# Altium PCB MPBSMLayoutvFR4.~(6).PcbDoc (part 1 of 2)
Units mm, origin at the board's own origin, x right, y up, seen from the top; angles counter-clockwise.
Board outline 131.7 x 110.39 mm, 4 copper layers (Top Layer, Power, GroundPlane, Bottom Layer), stack 2.286 mm thick; 158 components, 77 nets, 433 pads, 117 vias.
Unrouted connection lines stored in the file: 49.
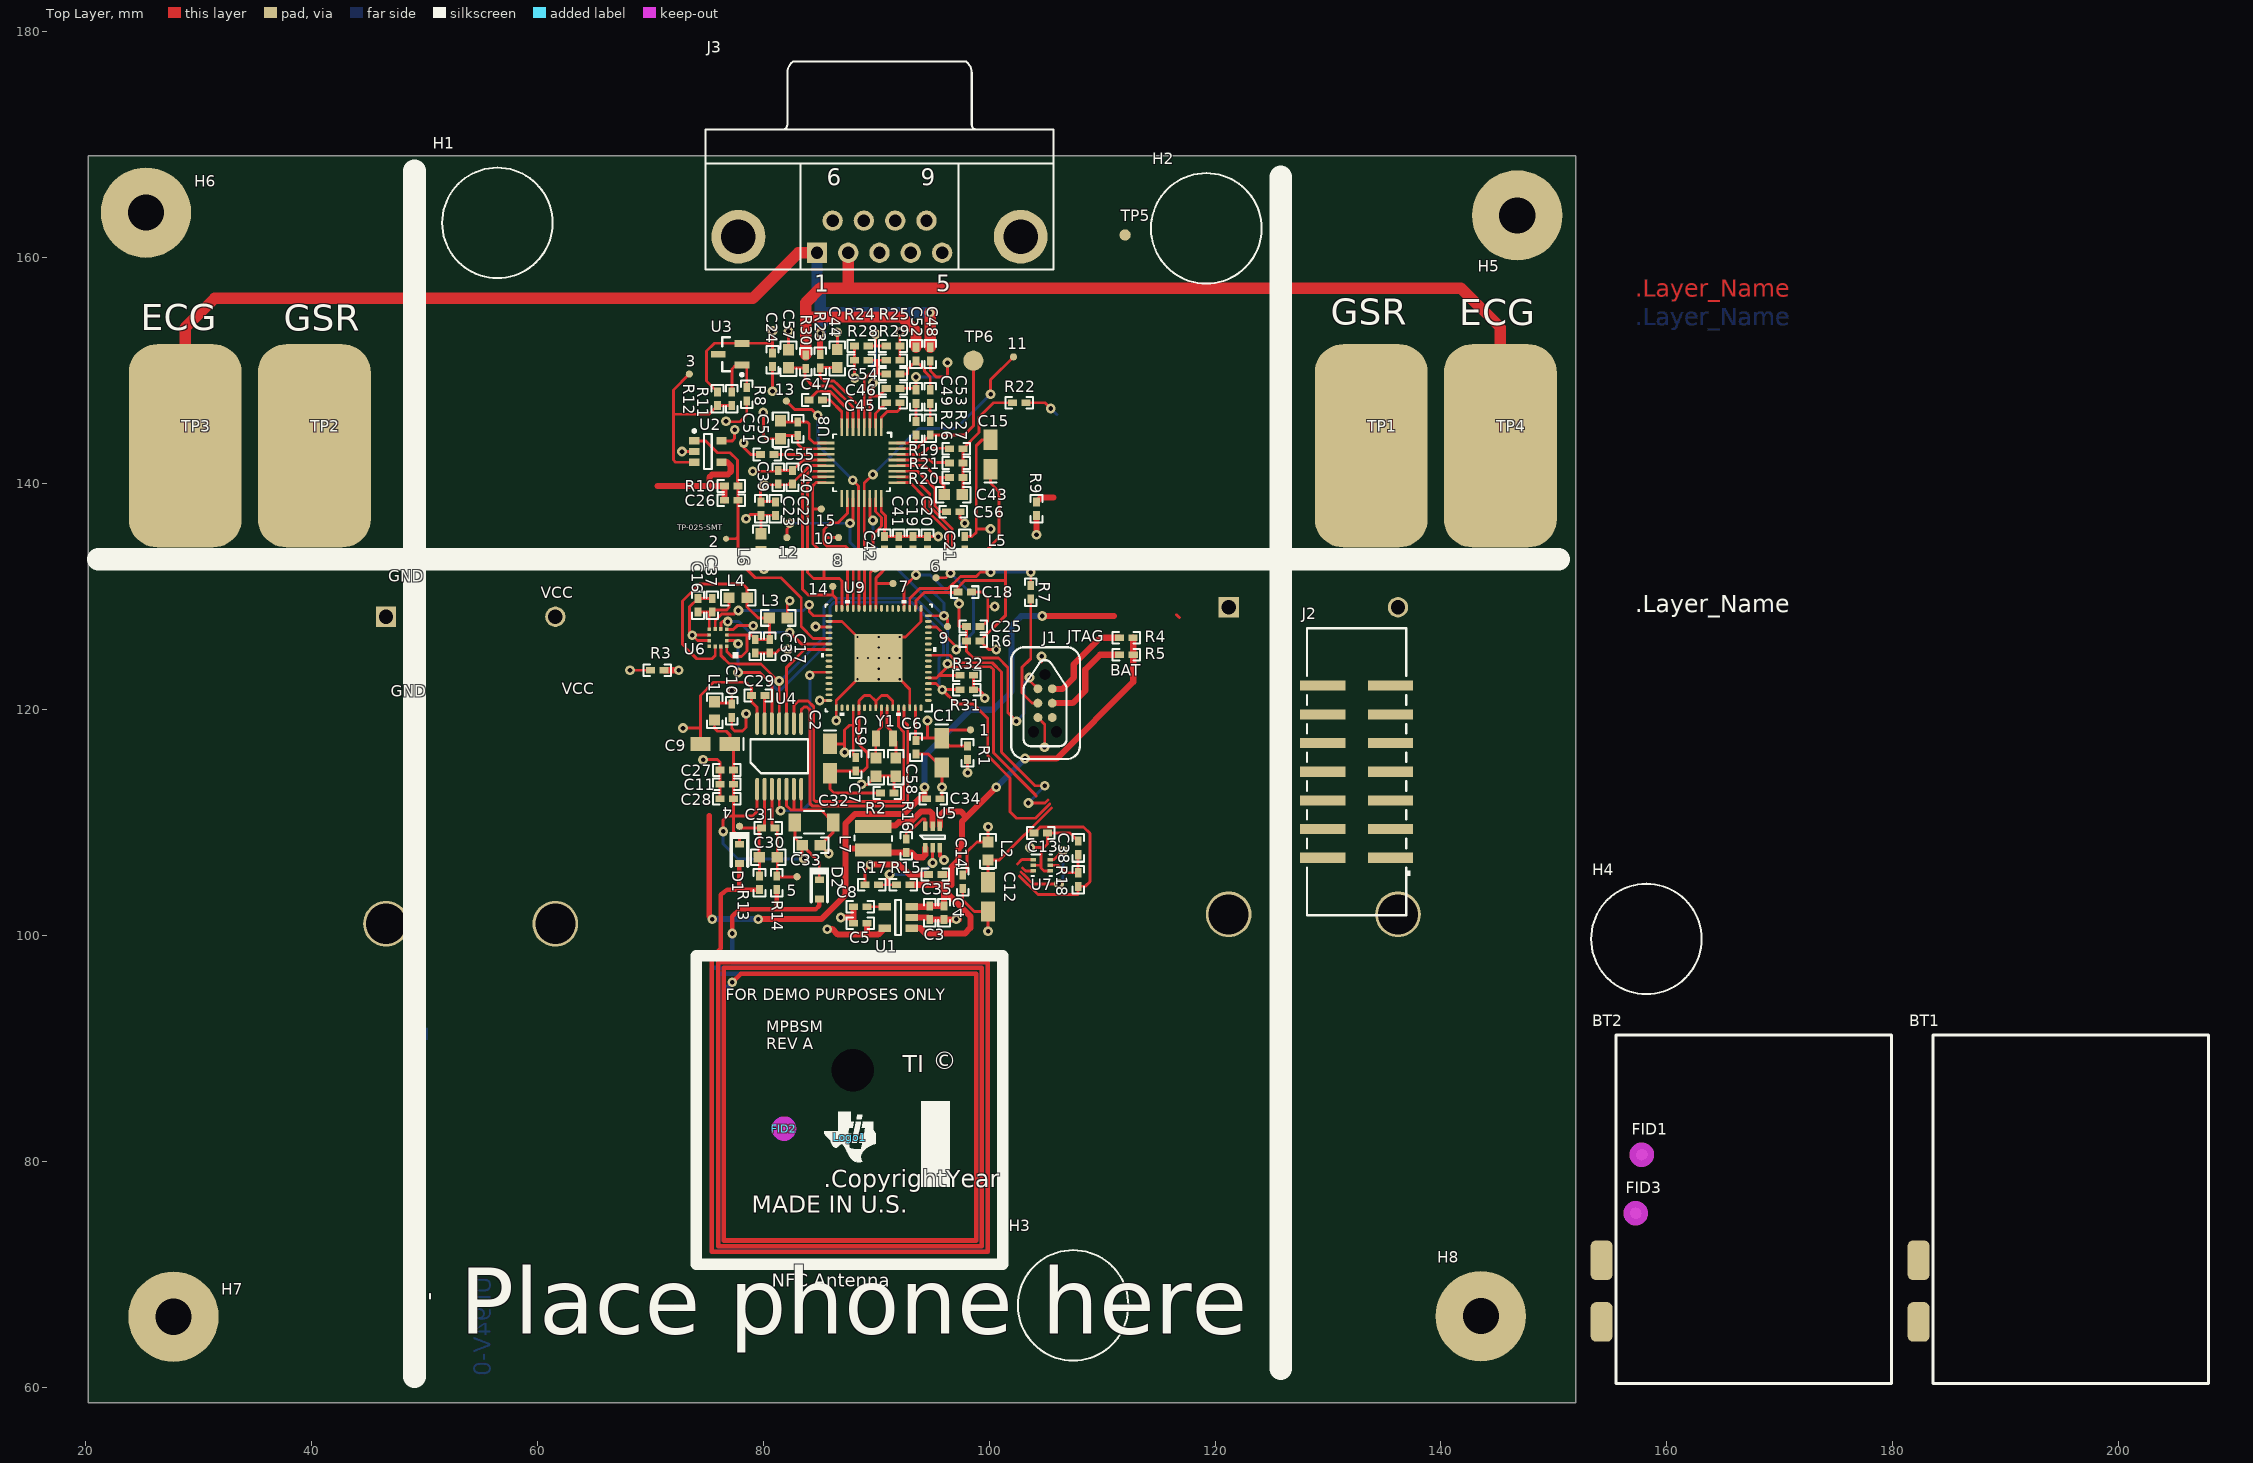
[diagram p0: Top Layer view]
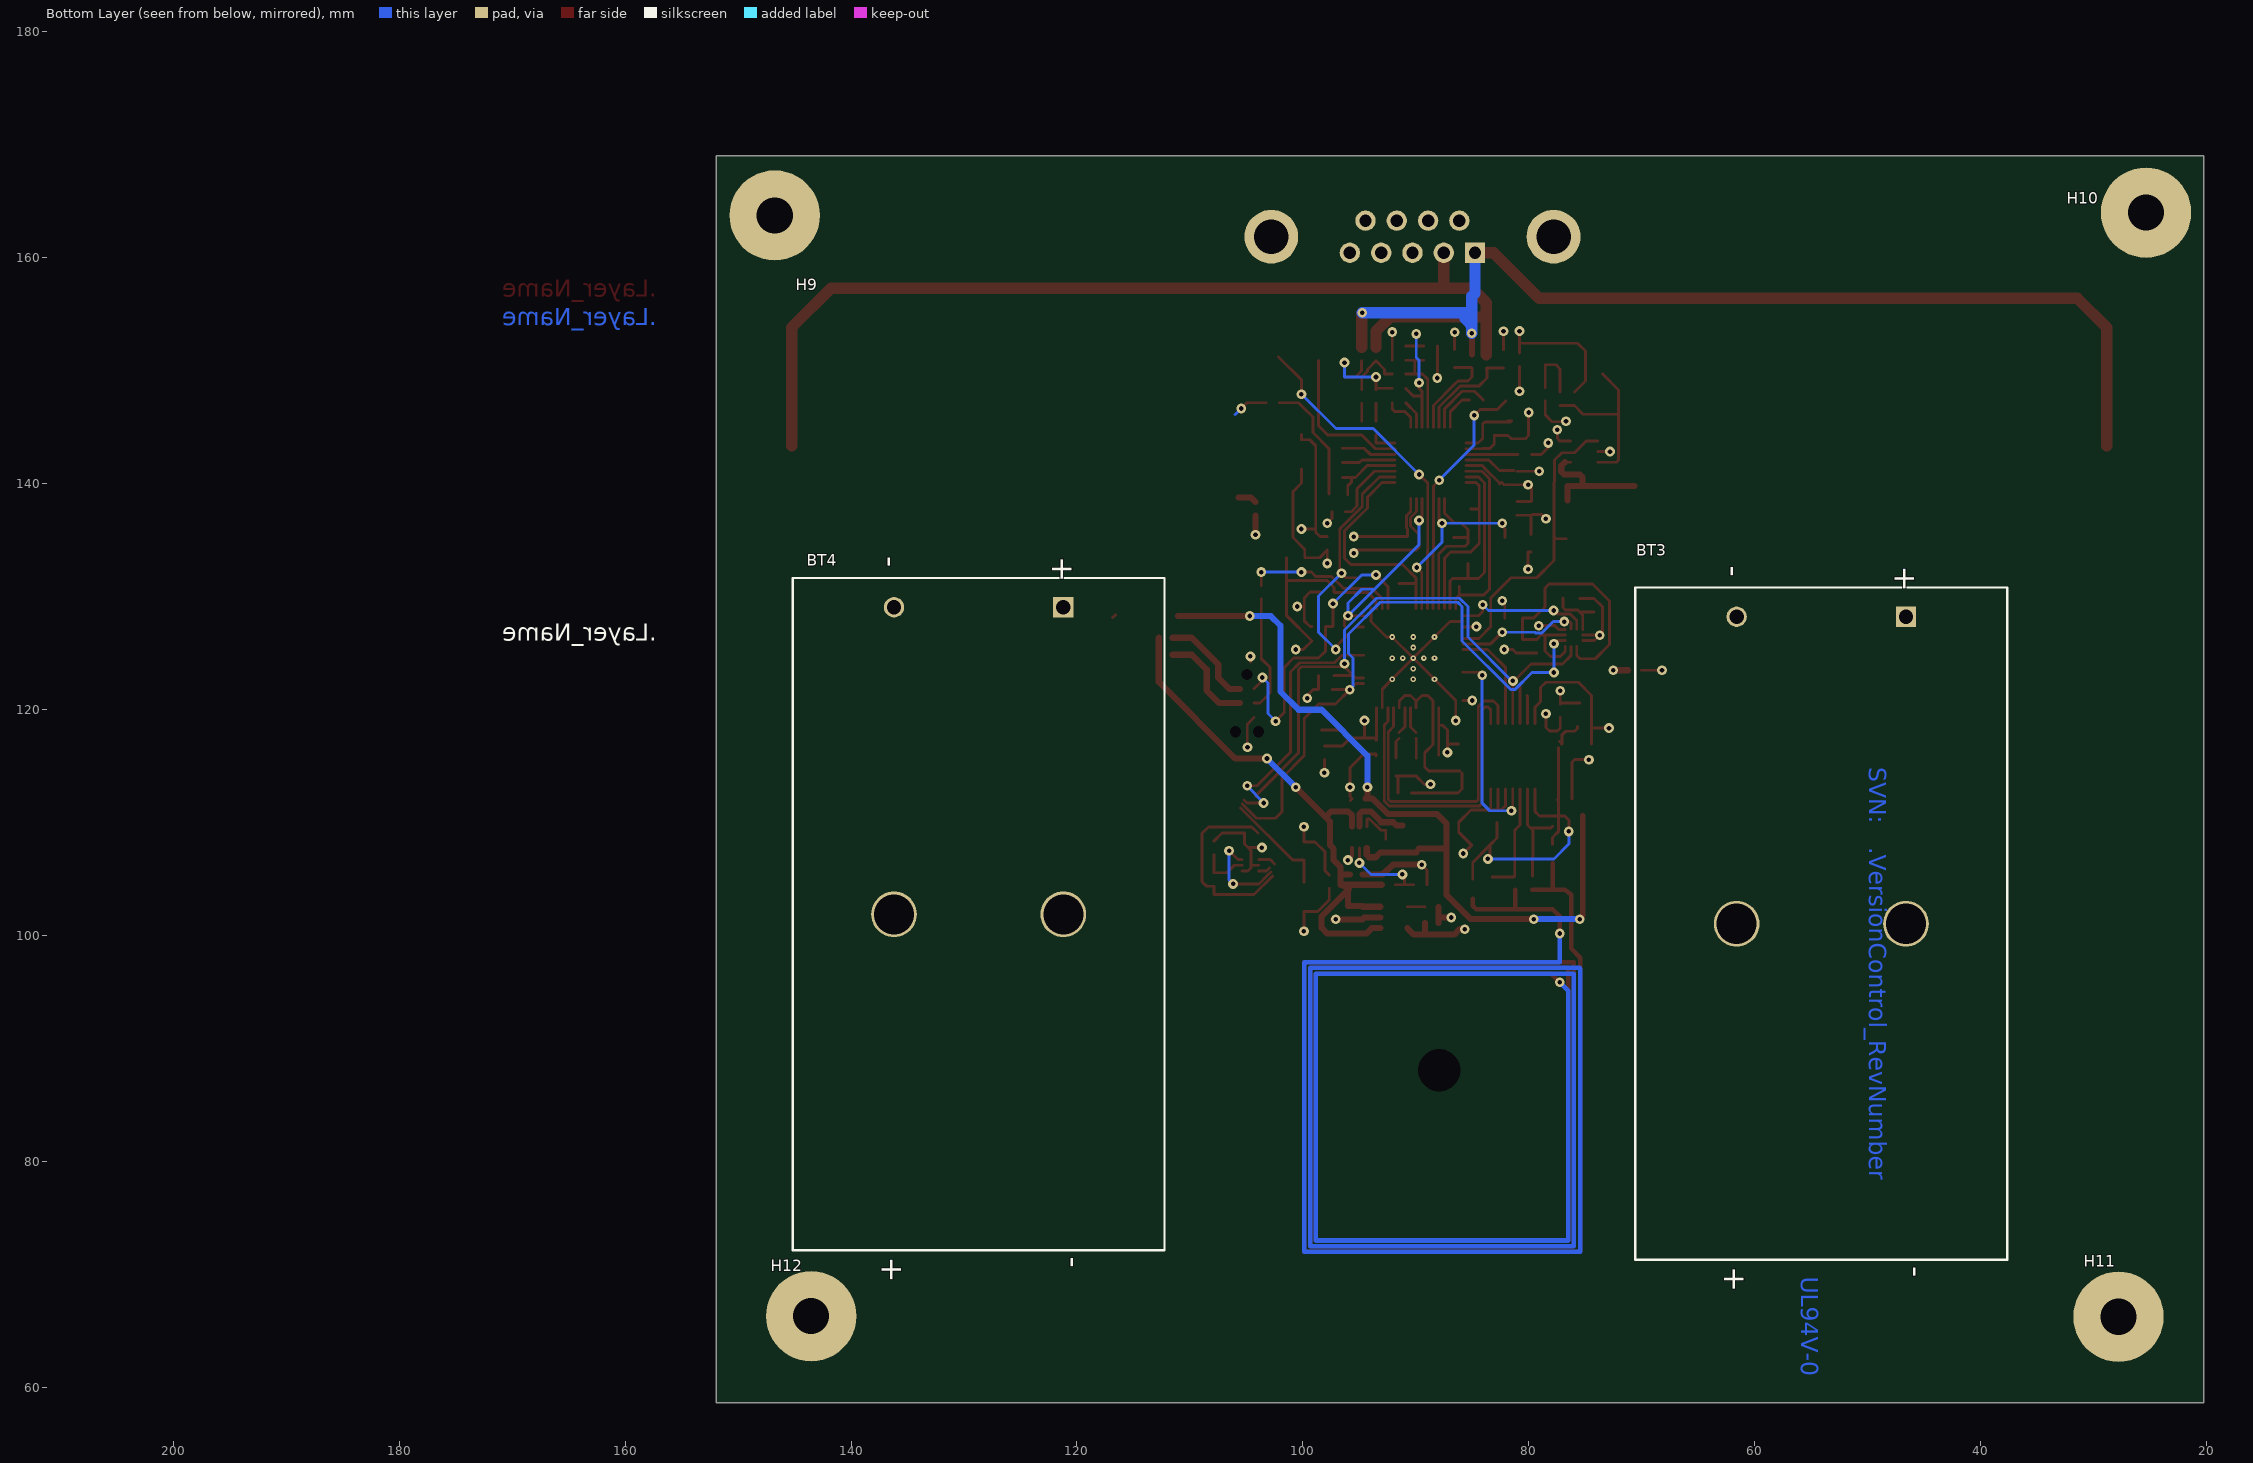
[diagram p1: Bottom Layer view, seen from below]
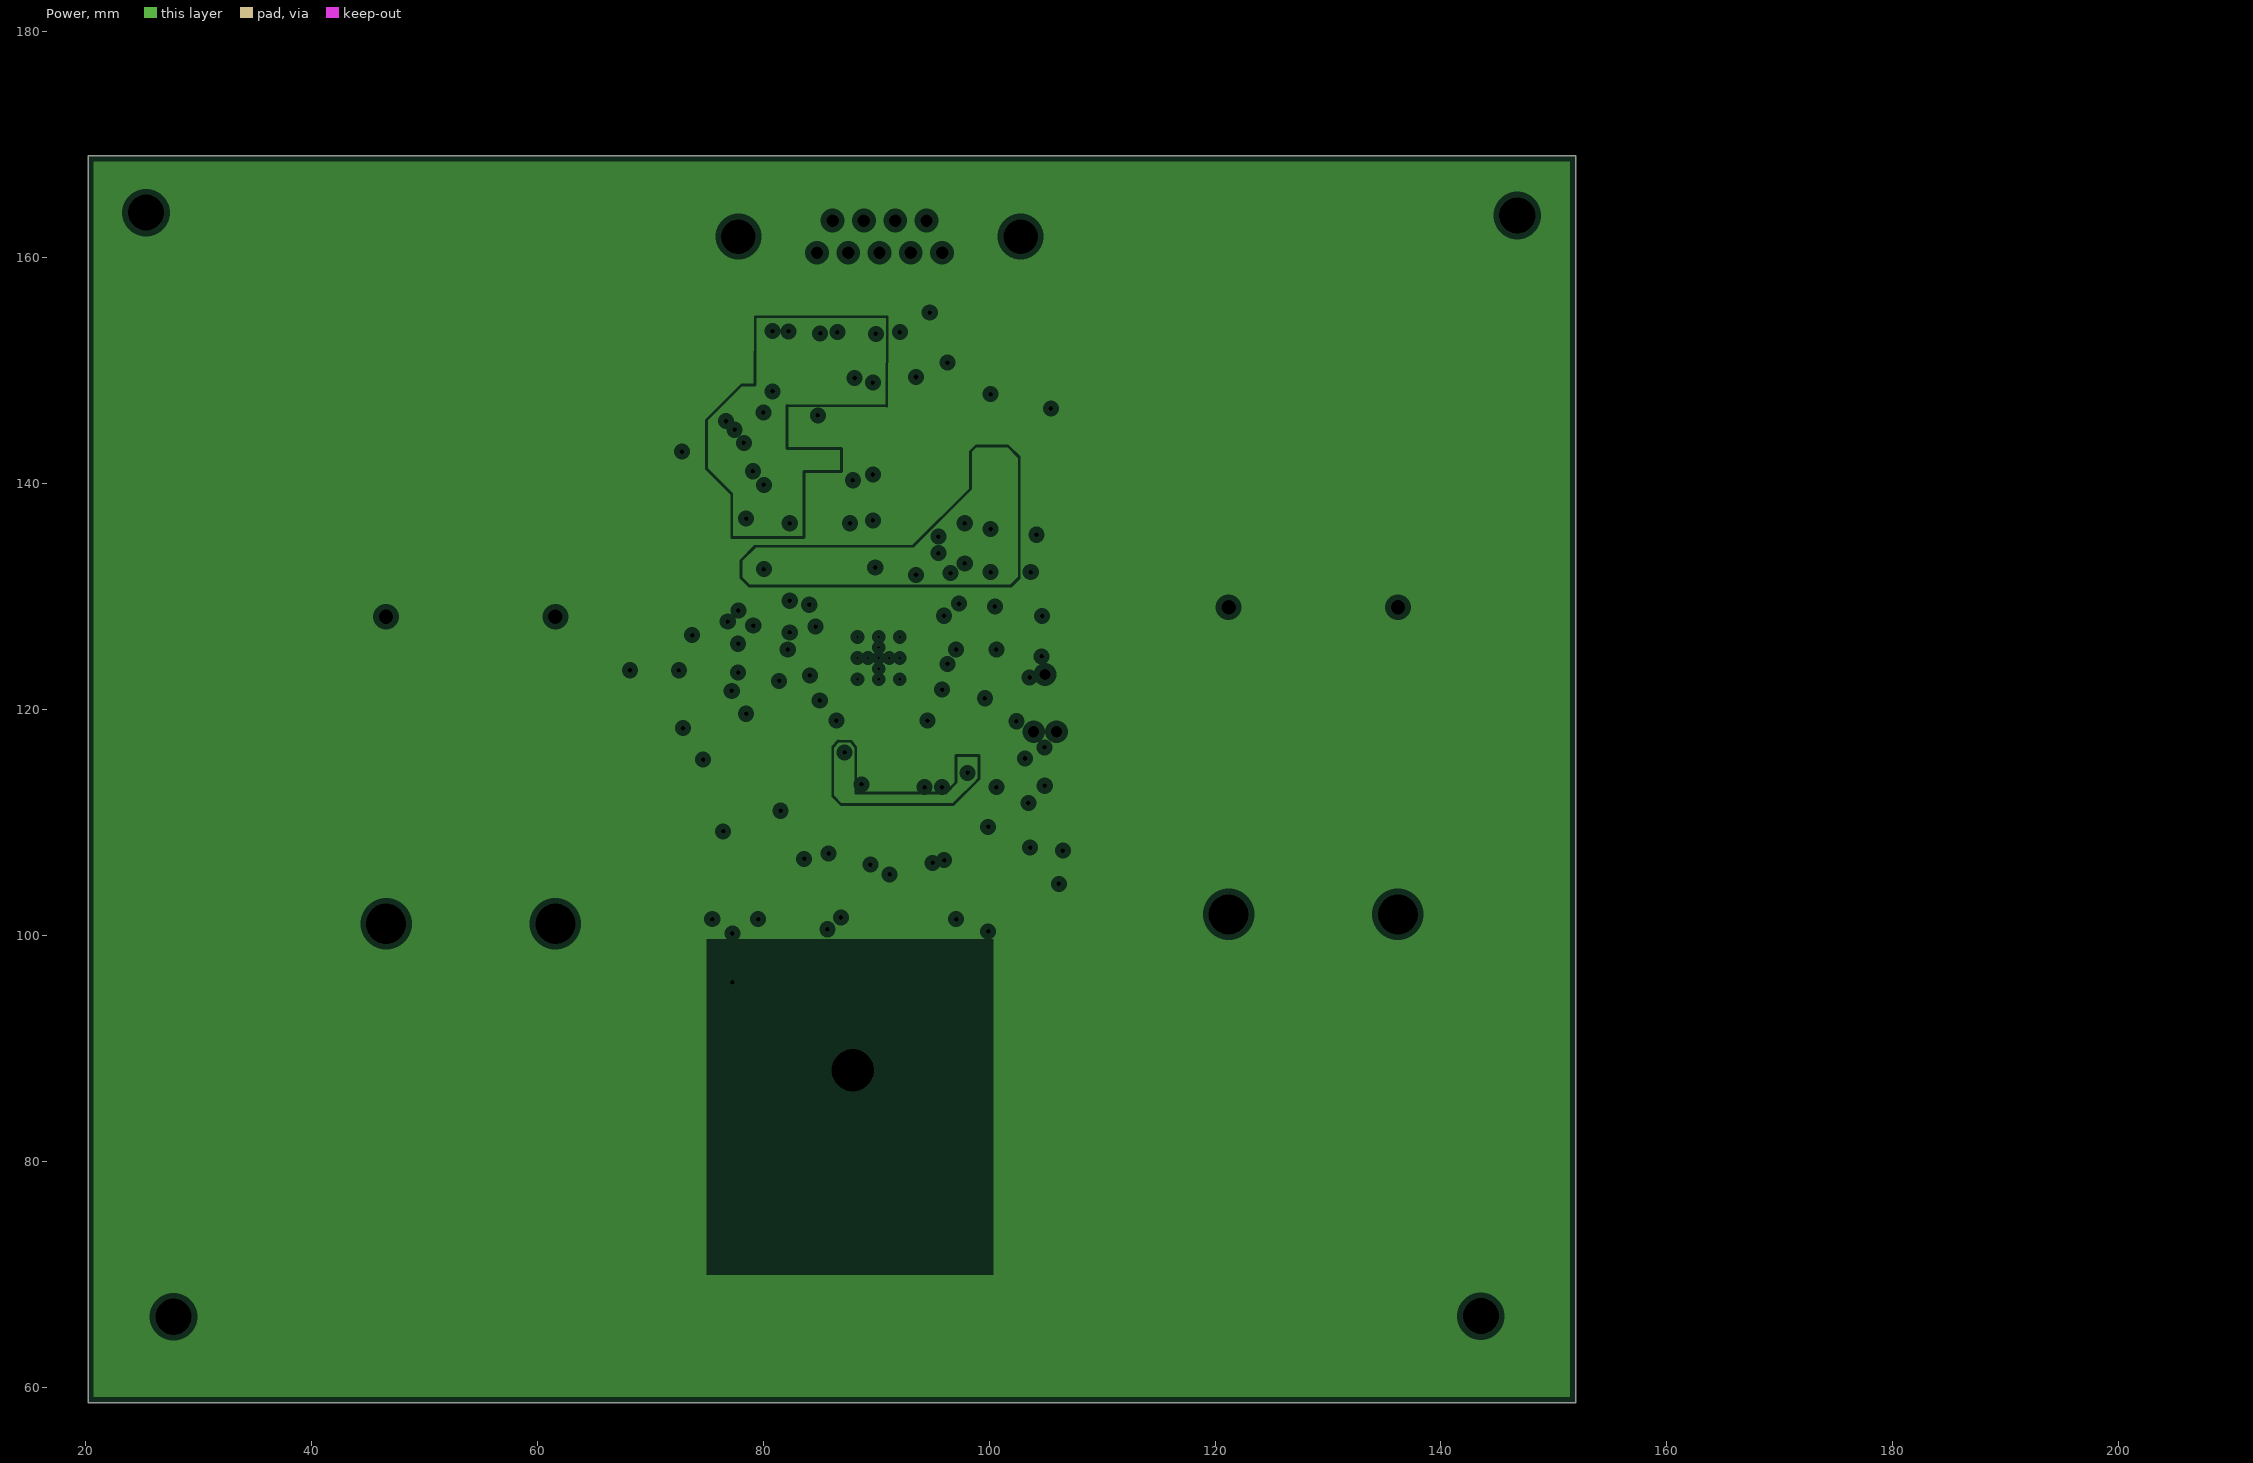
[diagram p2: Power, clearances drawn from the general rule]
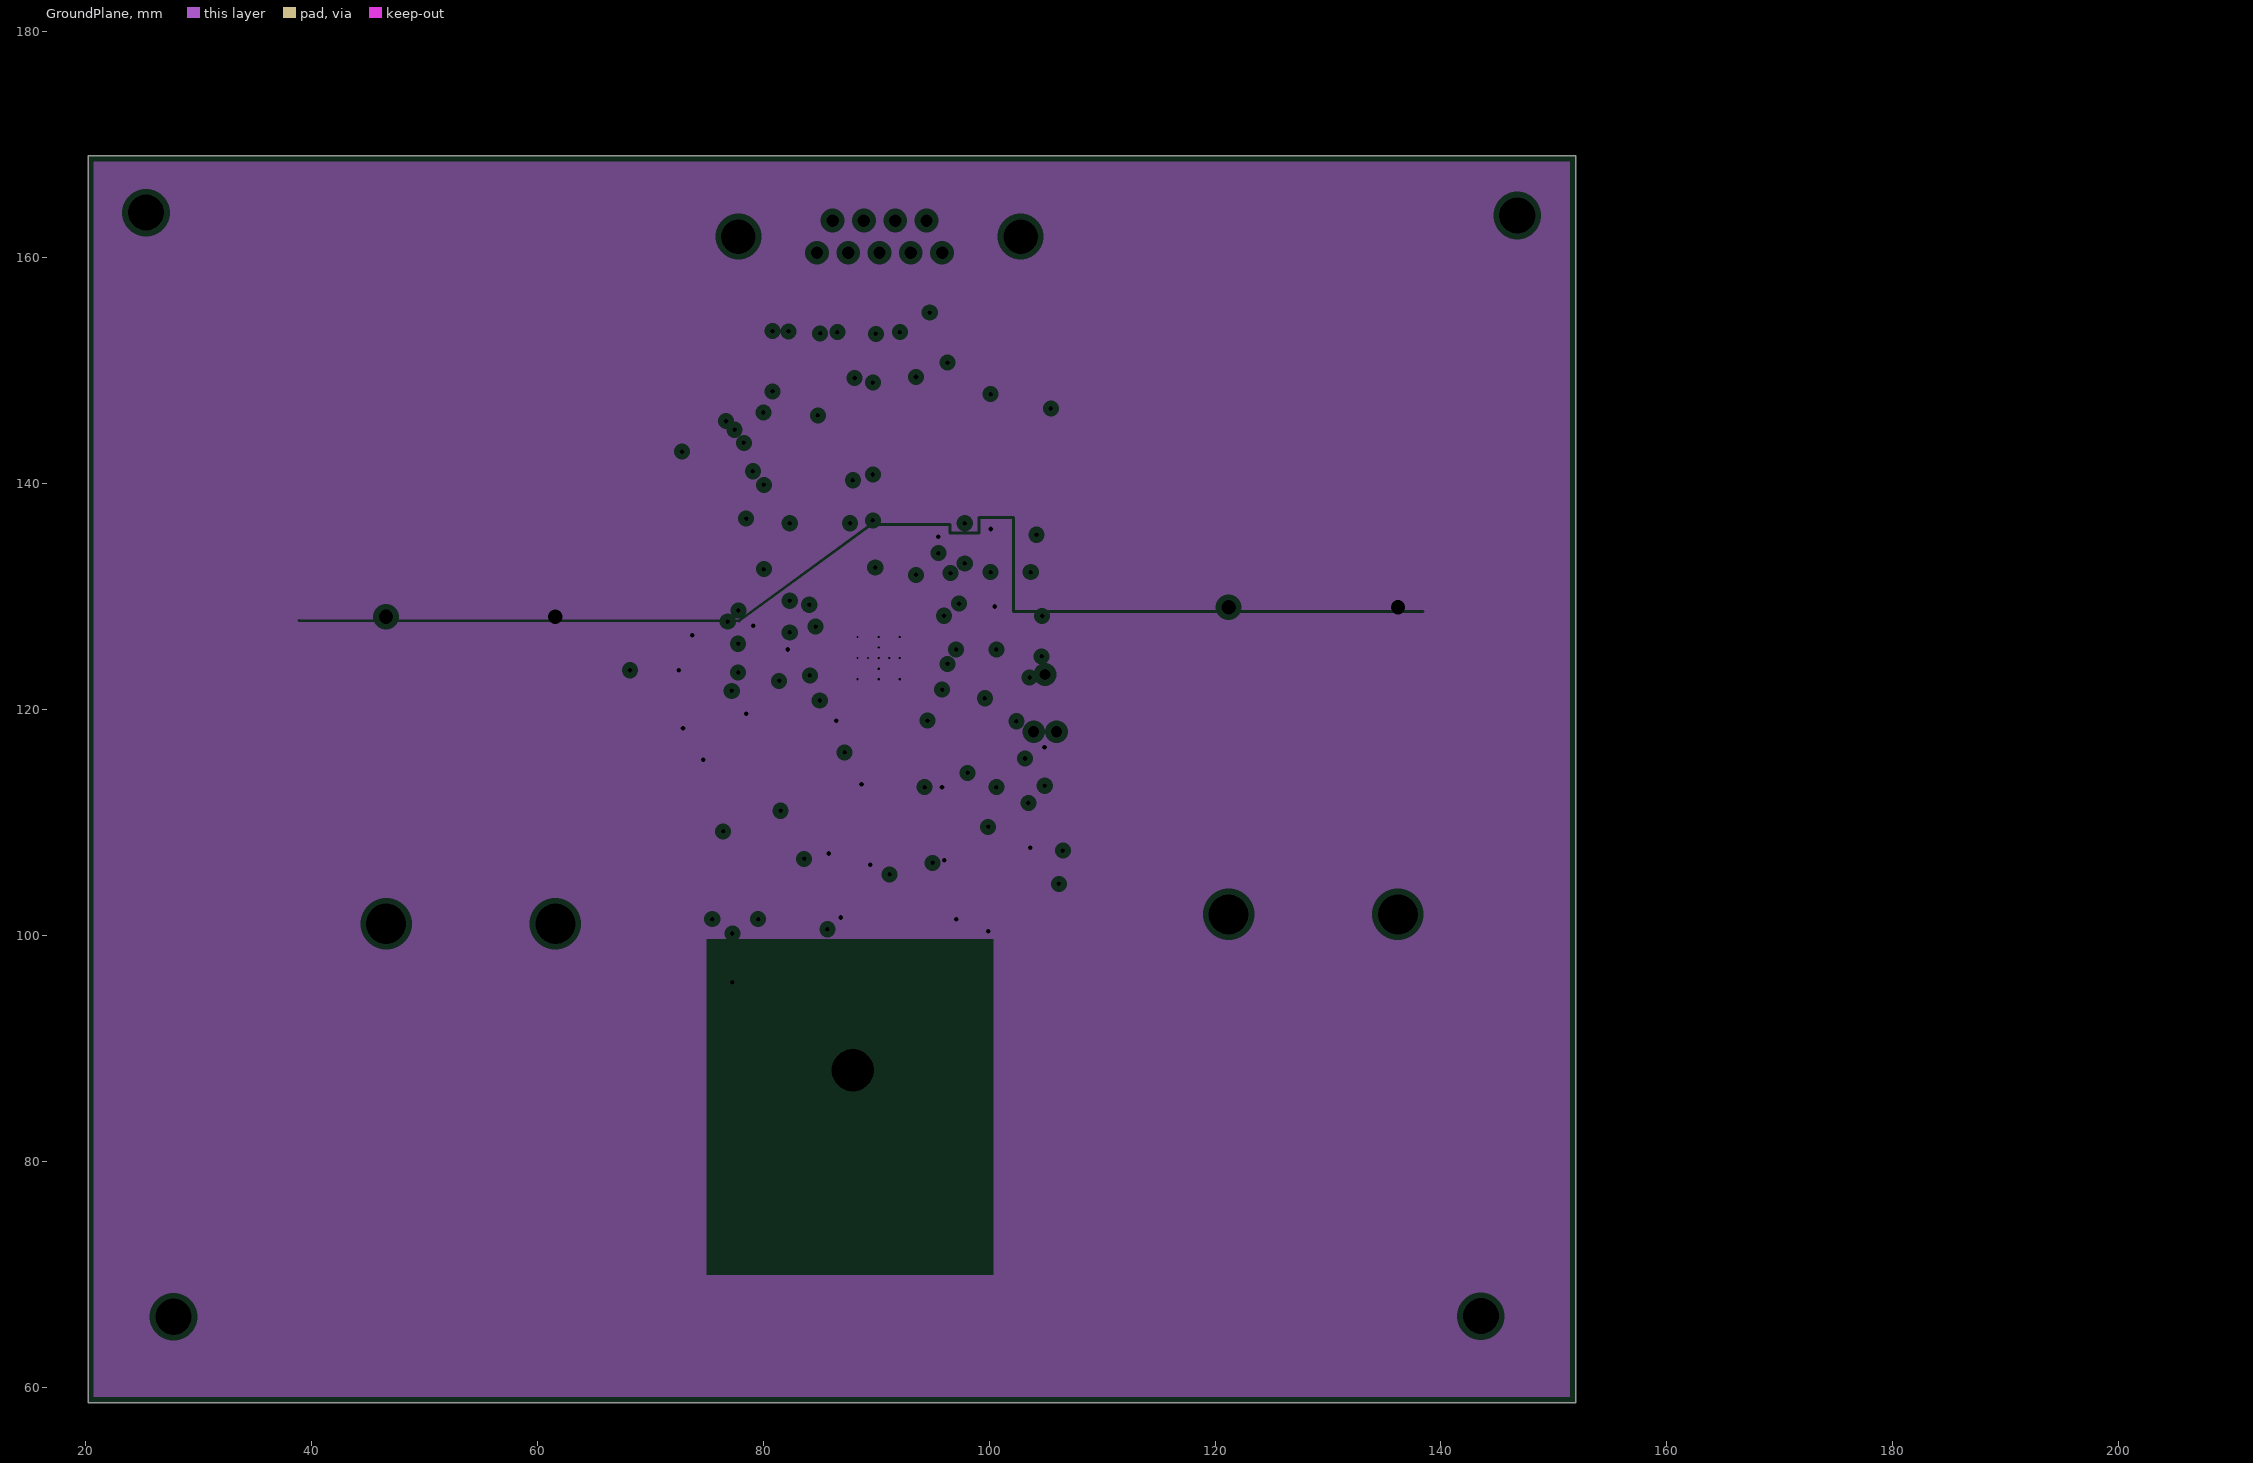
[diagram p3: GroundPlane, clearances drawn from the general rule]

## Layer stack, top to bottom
Top Solder: solder mask 0.0102, Solder Resist, Dk 3.5
Top Layer: signal copper 0.0356
Dielectric1: core 1.5037, FR-4, Dk 4.8
Power: plane copper 0.0356
Dielectric2: prepreg 0.32, FR-4, Dk 4.8
GroundPlane: plane copper 0.0356, net GND
Dielectric3: core 0.32, FR-4, Dk 4.8
Bottom Layer: signal copper 0.0356
Bottom Solder: solder mask 0.0102, Solder Resist, Dk 3.5

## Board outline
20.218,169.037 20.218,58.649 150.825,58.649 151.917,58.649 151.917,158.471 151.917,169.037 20.218,169.037

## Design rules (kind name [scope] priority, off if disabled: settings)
AcuteAngle [All] p1: minimum=4.50000000000000E+0001 checktracksonly=FALSE
AssemblyTestPointUsage [All] p1: valid=2
Clearance Clearance_BoardEdge_MountingHoles [OnCopper and InComponentClass('Mounting Holes') vs IsKeepOut] p1: gap=1.016
Clearance Clearance_BoardEdge_Poly [OnCopper and InPoly vs IsKeepOut] p2: gap=0.635
Clearance Clearance_BoardEdge [OnCopper and Not InComponentClass('Logo') and not InComponentClass('FiducialMark') and not InRegion(1000,500,4000,800) and Not IsKeepout vs IsKeepOut] p3: gap=1.905
Clearance Clearance_Poly [InPolygon] p4: gap=0.635
Clearance [All] p5: gap=0.1
ComponentClearance ComponentClearance_Shunt [InComponentClass('Header') vs InComponentClass('Shunt')] p1: gap=0 collisioncheckmode=3 verticalgap=0 showdistances=FALSE
ComponentClearance ComponentClearance_MountingHoles_FiducialMarks [InComponentClass('Mounting Holes') vs InComponentClass('FiducialMark')] p2: gap=1.27 collisioncheckmode=3 verticalgap=0.254 showdistances=FALSE
ComponentClearance ComponentClearance_Logo [InComponentClass('Logo')] p3: gap=1.27 collisioncheckmode=3 verticalgap=0.254 showdistances=FALSE
ComponentClearance ComponentClearance_ScrewToNut [(HasFootprint('NY PMS 440 0025 PH')) vs (HasFootprint('Keystone_1902C'))] p4: gap=0.127 collisioncheckmode=3 verticalgap=0.254 showdistances=FALSE
ComponentClearance ComponentClearance_MountingHoles [InComponentClass('Mounting Holes')] p5: gap=6.35 collisioncheckmode=3 verticalgap=2540 showdistances=FALSE
ComponentClearance ComponentClearance_SmallPassives [HasFootprint('0201*') or HasFootprint('0402*') or HasFootprint('0508') or HasFootprint('0603*') or HasFootprint('0612') or HasFootprint('0805*') or HasFootprint('0815*') or HasFootprint('0830*') or HasFootprint('1206*') or HasFootprint('1210*') or HasFootprint('1808*') or HasFootprint('1812*') or HasFootprint('1825*') or HasFootprint('2010*') or HasFootprint('2220*') or HasFootprint('2225*') or HasFootprint('2512*') or HasFootprint('2728*') or HasFootprint('3518*') vs HasFootprint('0201*') or HasFootprint('0402*') or HasFootprint('0508') or HasFootprint('0603*') or HasFootprint('0612') or HasFootprint('0805*') or HasFootprint('0815*') or HasFootprint('0830*') or HasFootprint('1206*') or HasFootprint('1210*') or HasFootprint('1808*') or HasFootprint('1812*') or HasFootprint('1825*') or HasFootprint('2010*') or HasFootprint('2220*') or HasFootprint('2225*') or HasFootprint('2512*') or HasFootprint('2728*') or HasFootprint('3518*')] p6: gap=0.508 collisioncheckmode=3 verticalgap=0.254 showdistances=FALSE
ComponentClearance ComponentClearance_THtoSMT [IsThruComponent vs IsSMTComponent] p7: gap=2.54 collisioncheckmode=3 verticalgap=0.762 showdistances=FALSE
ComponentClearance ComponentClearance_THtoTH [IsThruComponent vs IsThruComponent] p8: gap=3 collisioncheckmode=3 verticalgap=0.762 showdistances=FALSE
ComponentClearance [All] p9: gap=1.016 collisioncheckmode=3 verticalgap=0.254 showdistances=FALSE
DiffPairsRouting [All] p1: maxlimit=2.54 minlimit=0.254 mostfreqgap=0.254 toplayer_minwidth=0.381 toplayer_maxwidth=0.381 toplayer_prefwidth=0.381 bottomlayer_minwidth=0.381 bottomlayer_maxwidth=0.381 bottomlayer_prefwidth=0.381 maxuncoupledlength=25.4
FabricationTestPointUsage TestPointUsage [All] p1: valid=2 allowmultiple=FALSE
FabricationTestpoint Testpoint [All] p1: side=3 testpointundercomponent=TRUE minsize=1.016 maxsize=2.54 preferedsize=1.524 minholesize=0 maxholesize=1.016 preferedholesize=0.813 testpointgrid=0.025 allowsidetop=TRUE allowsidebottom=TRUE usegrid=TRUE gridtolerance=0
FanoutControl Fanout_LCC [IsLCC] p1: bgadir=Out bgaviamode=Centered fanoutstyle=Auto fanoutdirection=Alternating viagrid=0.025 // Fanout_LCC (Default Rule)
FanoutControl Fanout_BGA [IsBGA] p2: bgadir=Out bgaviamode=Centered fanoutstyle=Auto fanoutdirection=Alternating viagrid=0.025 // Fanout_BGA (Default Rule)
FanoutControl Fanout_Default [All] p4: bgadir=Out bgaviamode=Centered fanoutstyle=Auto fanoutdirection=Alternating viagrid=0.025 // Fanout_Default (Default Rule)
FanoutControl Fanout_Small [(CompPinCount < 5)] p5: bgadir=Out bgaviamode=Centered fanoutstyle=Auto fanoutdirection=OutThenIn viagrid=0.025 // Fanout_Small (Default Rule)
Height [All] p1: minheight=0 maxheight=55.4 prefheight=12.7
HoleSize [All] p1: absolutevalues=TRUE maxlimit=6.375 minlimit=0.1 maxpercent=80.000 minpercent=20.000
MinimumAnnularRing MinimumAnnularRing_ThermalPadVias [IsVia and InAnyComponent] p1: minimumring=0.15
MinimumAnnularRing [All] p2: minimumring=0.229
MinimumSolderMaskSliver MinimumSolderMaskSliver_Logo [InComponentClass('Logo') vs InComponentClass('Logo')] p1: minsoldermaskwidth=0.018
MinimumSolderMaskSliver [All] p2: minsoldermaskwidth=0.08
PlaneClearance [All] p1: clearance=0.508
PlaneConnect [All] p1: planeconnectstyle=Relief reliefexpansion=0.254 reliefentries=4 reliefconductorwidth=0.254 reliefairgap=0.254
PolygonConnect [All] p1: connectstyle=Relief reliefconductorwidth=0.254 reliefentries=4 polygonreliefangle="90 Angle" airgapwidth=0.254
RoutingVias ThermalPadVias [IsVia and InAnyComponent] p1: holewidth=0.2 width=0.5 viastyle="Through Hole" minholewidth=0.2 minwidth=0.5 maxholewidth=0.33 maxwidth=0.6
RoutingVias [All] p2: holewidth=0.406 width=0.864 viastyle="Through Hole" minholewidth=0.2 minwidth=0.66 maxholewidth=1.016 maxwidth=1.651
SMDToCorner [All] p1: distance=30000
SilkToSilkClearance SilkToSilkClearance_Pb-FreeLogo [(HasFootprint('Pb-Free_Overlay_Medium') OR HasFootprint('Pb-Free_Overlay_Small')) vs (HasFootprint('Pb-Free_Overlay_Medium') OR HasFootprint('Pb-Free_Overlay_Small'))] p1: silktosilkclearance=0
SilkToSilkClearance [All] p2: silktosilkclearance=0
SilkToSolderMaskClearance SilkscreenOverComponentPads [IsPad] p1: minsilkscreentomaskgap=0.127 clearancetoexposedcopper=TRUE
SolderMaskExpansion [All] p1: expansion=0.05
Width [All] p1: maxlimit=2.54 minlimit=0.152 preferedwidth=0.254 checkconnectedcopper=TRUE
14 further rules are at their usual default settings.

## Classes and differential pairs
component class Logo: Logo1
component class Designator: FID1 FID2 FID3 H1 H2 H3 H4 H5 H6 H7 H8 H9 H10 H11 H12 Logo1 ZZ1 ZZ2 ZZ3 ZZ4
component class FiducialMark: FID1 FID2 FID3
component class AssemblyNote: ZZ1 ZZ2 ZZ3 ZZ4
component class Battery: BT1 BT2 BT3 BT4 U?
component class BMA280: C36 C37 U6
component class "Boost Converter": C34 C35 L7 R15 R16 R17 U5
component class ECG: 6 7 8 9 10 11 12 13 14 15 C39 C40 C41 C42 C43 C44 C45 C46 C47 C48 C49 C50 C51 C52 C53 C54 C55 C56 C57 R19 R20 R21 R22 R23 R24 R25 R26 R27 R28 R29 R30 TP6 U8
component class GSR: 2 3 C26 R8 R9 R10 R11 R12 U2 U3
component class "JTAG SPY-BY-WIRE": C25 J1 J2 R4 R5 R6 R7
component class MSP430FR5XXX: C58 C59 R31 R32 U9 Y1
component class "Power Filtering": 1 C1 C2 C3 C4 C5 C6 C7 C8 C9 C10 C11 C12 C13 C14 C15 C16 C17 C18 C19 C20 C21 C22 C23 C24 L1 L2 L3 L4 L5 L6 R1 R2 R3 U1
component class Temperature: C38 R18 U7
component class Transponder: 4 5 C27 C28 C29 C30 C31 C32 C33 D1 D2 R13 R14 U4
component class "Analog Connector": J3
component class "Mounting Holes": H5 H6 H7 H8

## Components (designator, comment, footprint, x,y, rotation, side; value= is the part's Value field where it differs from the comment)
1 "TP-025-SMT" TP_25MIL-SMT#1 98.349,118.212 r90 top
2 "TP-025-SMT" TP_25MIL-SMT#2 76.708,135.128 r0 top
3 "TP-025-SMT" TP_25MIL-SMT#1 73.457,149.708 r0 top
4 "TP-025-SMT" TP_25MIL-SMT#1 77.897,109.676 r0 top
5 "TP-025-SMT" TP_25MIL-SMT#1 82.982,105.207 r270 top
6 "TP-025-SMT" TP_25MIL-SMT#1 95.301,131.674 r0 top
7 "TP-025-SMT" TP_25MIL-SMT#1 91.491,131.166 r0 top
8 "TP-025-SMT" TP_25MIL-SMT#1 85.395,133.198 r0 top
9 "TP-025-SMT" TP_25MIL-SMT#1 96.317,127.356 r0 top
10 "TP-025-SMT" TP_25MIL-SMT#1 86.665,135.23 r0 top
11 "TP-025-SMT" TP_25MIL-SMT#1 102.159,151.232 r0 top
12 "TP-025-SMT" TP_25MIL-SMT#1 82.093,135.23 r0 top
13 "TP-025-SMT" TP_25MIL-SMT#1 82.042,147.32 r0 top
14 "TP-025-SMT" TP_25MIL-SMT#1 86.157,130.912 r90 top
15 "TP-025-SMT" TP_25MIL-SMT#1 85.141,137.77 r0 top
BT1 "XXXXXX" Flat_Battery 182.423,68.453 r90 top
BT2 "XXXXXX" Flat_Battery 154.356,68.453 r90 top
BT3 "2462" Keystone_2462 54.102,114.63 r270 bottom
BT4 "2462" Keystone_2462 128.702,115.468 r270 bottom
C1 "293D106X9010A2TE3" 3216-18 95.809,116.18 r270 top
C2 "293D106X9010A2TE3" 3216-18 85.903,115.672 r270 top
C3 "C1005X5R1A104K" 0402 94.747,102.028 r270 top
C4 "C1005X5R0J105M" 0402 96.017,102.028 r270 top
C5 "C1005X5R1C225K050BC" 0402 88.6,101.092 r180 top
C6 "C1005X5R1A104K" 0402 93.523,116.688 r270 top
C7 "C1005X5R1A104K" 0402 88.189,115.164 r270 top
C8 "C1005X7R1E103K" 0402 88.595,102.54 r180 top
C9 "293D105X9016A2TE3" 3216-18 75.743,116.942 r180 top
C10 "C1005X5R1A104K" 0402 77.216,119.888 r270 top
C11 "C1005X5R1A104K" 0402 76.759,113.386 r180 top
C12 "293D106X9010A2TE3" 3216-18 99.906,103.422 r270 top
C13 "C1005X5R1A104K" 0402 104.582,109.068 r0 top
C14 "C1005X5R1A104K" 0402 97.665,104.75 r270 top
C15 "293D105X9016A2TE3" 3216-18 100.127,142.596 r90 top
C16 "CL05A106MQ5NUNC" 0402 74.219,129.247 r90 top
C17 "CL05A106MQ5NUNC" 0402 80.569,125.624 r270 top
C18 "C1005X5R1A104K" 0402 97.841,130.404 r0 top
C19 "C1005X5R1A104K" 0402 93.269,134.722 r90 top
C20 "C1005X5R1C225K050BC" 0402 94.539,134.722 r90 top
C21 "CL05A106MQ5NUNC" 0402 97.841,134.722 r90 top
C22 "CL05A106MQ5NUNC" 0402 81.077,137.77 r90 top
C23 "C1005X5R1A104K" 0402 79.807,137.77 r90 top
C24 "C1005X5R1A104K" 0402 80.823,150.978 r90 top
C25 "C1005X8R1H222K" 0402 98.603,127.356 r0 top
C26 "C1005X7R1E103K" 0402 77.175,138.532 r180 top
C27 "C1005X5R0J105M" 0402 76.759,114.656 r180 top
C28 "C1005X5R1A104K" 0402 76.759,112.116 r180 top
C29 "GRM155R60J474KE19D" 0402 79.553,121.26 r0 top
C30 "C1608C0G1H330J" 0603 80.437,106.941 r0 top
C31 "GRM1555C1H390JA01D" 0402 80.437,109.515 r0 top
C32 "C3216X5R1A107M160AC" 1206_190 84.501,110.023 r0 top
C33 "Used in BOM report" 0603 84.247,107.991 r0 top
C34 "CL05A106MQ5NUNC" 0402 95.047,112.116 r0 top
C35 "CL05A106MQ5NUNC" 0402 95.25,105.41 r180 top
C36 "C1005X5R1A104K" 0402 79.299,125.624 r270 top
C37 "C1005X5R1A104K" 0402 75.489,129.247 r90 top
C38 "C1005X7R1E103K" 0402 107.884,107.752 r90 top
C39 "C1005X5R1C105K050BC" 0402 81.331,140.564 r270 top
C40 "C1005X5R1A104K" 0402 82.601,140.564 r270 top
C41 "C1005X5R1C105K050BC" 0402 91.999,134.722 r90 top
C42 "C1005X5R1A104K" 0402 90.729,134.722 r90 top
C43 "C0603C152K5RACTU" 0603 96.825,139.04 r180 top
C44 "GRM1885C1H302JA01D" 0603 86.563,151.091 r90 top
C45 "GRM155R61A472KA01D" 0402 91.491,147.168 r0 top
C46 "C1005X8R1H222K" 0402 91.491,148.438 r0 top
C47 "GRM155R61A472KA01D" 0402 84.633,147.422 r180 top
C48 "C1005X5R1A104K" 0402 94.793,151.486 r270 top
C49 "C1005X8R1H222K" 0402 93.523,147.722 r90 top
C50 "C1005X5R1A104K" 0402 83.058,144.872 r270 top
C51 "C1608X5R0J106M" 0603 81.534,144.78 r270 top
C52 "C1005X5R1A104K" 0402 93.523,151.486 r270 top
C53 "C1005X8R1H222K" 0402 94.793,147.722 r90 top
C54 "C1005X8R1H222K" 0402 91.491,149.708 r0 top
C55 "C1005X5R1C105K050BC" 0402 80.361,142.596 r180 top
C56 "C1005X5R1C105K050BC" 0402 96.825,137.516 r0 top
C57 "GRM1885C1H302JA01D" 0603 82.241,151.063 r90 top
C58 "06035A100JAT2A" 0603 91.745,114.91 r270 top
C59 "06035A100JAT2A" 0603 89.992,114.91 r270 top
D1 "CDBU0130L" SOD-523F 77.897,107.229 r270 top
D2 "CDBU0130L" SOD-523F 84.963,104.089 r270 top
FID1 "Fiducial" Fiducial10-20 157.785,80.594 r0 top
FID2 "Fiducial" Fiducial10-20 81.839,82.906 r0 top
FID3 "Fiducial" Fiducial10-20 157.251,75.413 r0 top
H1 "SJ61A2" Bumpon_SJ61A2 56.464,163.093 r0 top
H2 "SJ61A2" Bumpon_SJ61A2 119.228,162.611 r0 top
H3 "SJ61A2" Bumpon_SJ61A2 107.442,67.259 r0 top
H4 "SJ61A2" Bumpon_SJ61A2 158.191,99.695 r0 top
H5 "NY PMS 440 0025 PH" "NY PMS 440 0025 PH" 146.761,163.754 r90 top
H6 "NY PMS 440 0025 PH" "NY PMS 440 0025 PH" 25.349,164.008 r90 top
H7 "NY PMS 440 0025 PH" "NY PMS 440 0025 PH" 27.788,66.243 r90 top
H8 "NY PMS 440 0025 PH" "NY PMS 440 0025 PH" 143.536,66.3 r90 top
H9 "1902C" Keystone_1902C 146.761,163.748 r90 bottom
H10 "1902C" Keystone_1902C 25.375,163.982 r90 bottom
H11 "1902C" Keystone_1902C 27.788,66.243 r90 bottom
H12 "1902C" Keystone_1902C 143.535,66.294 r180 bottom
J1 "TC2030-MCP-NL" TC2030-MCP-NL 104.953,120.574 r180 top
J2 "61201420621" Wurth_61201420621 132.537,114.503 r180 top
J3 "182-009-213R171" NORCOMP_182-009-213R171 90.297,171.374 r0 top
L1 "BLM18HG601SN1D" 0603 75.692,119.888 r270 top
L2 "BLM18HG601SN1D" 0603 99.906,107.486 r270 top
L3 "BLM18HG601SN1D" 0603 81.331,128.118 r180 top
L4 "BLM18HG601SN1D" 0603 77.775,129.896 r0 top
L5 "BLM18HG601SN1D" 0603 100.635,133.452 r180 top
L6 "BLM18HG601SN1D" 0603 79.807,134.772 r90 top
L7 "EPL3015-472MLB" EPL3015 89.738,108.61 r90 top
Logo1 "Texas Instruments" TI_Symbol_Overlay_Small 87.681,82.144 r0 top
R1 "ERJ-2GE0R00X" 0402 98.095,116.18 r270 top
R2 "ERJ-2GE0R00X" 0402 90.983,112.624 r180 top
R3 "ERJ-2GE0R00X" 0402 70.621,123.489 r180 top
R4 "ERJ-2GE0R00X" 0402 112.141,126.365 r0 top
R5 "ERJ-2GE0R00X" 0402 112.16,124.861 r0 top
R6 "CRCW040247K0JNED" 0402 98.603,126.086 r0 top
R7 "ERJ-2GE0R00X" 0402 103.683,130.404 r90 top
R8 "CRCW040221K5FKED" 0402 78.537,147.93 r270 top
R9 "CRCW040210K0FKED" 0402 104.191,137.77 r90 top
R10 "ERJ-2RKF1004X" 0402 77.175,139.802 r0 top
R11 "CRCW040211K8FKED" 0402 77.221,147.517 r90 top
R12 "CRCW04028K06FKED" 0402 75.951,147.517 r270 top
R13 "ERJ-2GE0R00X" 0402 79.675,104.655 r270 top
R14 "ERJ-2GE0R00X" 0402 81.199,104.655 r270 top
R15 "ERJ-2RKF1004X" 0402 92.415,104.496 r0 top
R16 "ERJ-2GE0R00X" 0402 92.659,107.95 r90 top
R17 "ERJ-2RKF2003X" 0402 89.621,104.496 r0 top
R18 "CRCW04024K99FKED" 0402 107.884,104.958 r270 top
R19 "ERJ-2GE0R00X" 0402 97.079,143.104 r0 top
R20 "ERJ-2RKF1004X" 0402 97.079,140.564 r0 top
R21 "ERJ-2RKF1003X" 0402 97.079,141.834 r0 top
R22 "ERJ-2RKF1003X" 0402 102.667,147.168 r0 top
R23 "CRCW040251K1FKED" 0402 85.039,150.837 r270 top
R24 "CRCW040210M0FKED" 0402 88.697,152.202 r180 top
R25 "CRCW040210M0FKED" 0402 91.491,152.202 r180 top
R26 "CRCW040240K2FKED" 0402 93.523,144.928 r270 top
R27 "CRCW040240K2FKED" 0402 94.793,144.928 r270 top
R28 "CRCW040210M0FKED" 0402 88.697,150.932 r180 top
R29 "CRCW040210M0FKED" 0402 91.491,150.932 r180 top
R30 "CRCW040251K1FKED" 0402 83.765,150.809 r270 top
R31 "CRCW04023K30JNED" 0402 98.003,121.768 r180 top
R32 "CRCW04023K30JNED" 0402 98.003,123.038 r180 top
TP1 "TESTPOINT" TP_SM_1MM#1 133.833,143.358 r0 top
TP2 "TESTPOINT" TP_SM_1MM#2 40.259,143.358 r90 top
TP3 "TESTPOINT" TP_SM_1MM#2 28.829,143.358 r90 top
TP4 "TESTPOINT" TP_SM_1MM#2 145.263,143.358 r90 top
TP5 "TESTPOINT" TP_SM_1MM#3 112.039,162.027 r90 top
TP6 "Pogo Pad" PogoPad 98.603,150.901 r0 top
U1 "TPS73030DBVR" DBV0005A_N 91.948,101.6 r180 top
U2 "LMP2231AMFE" MF05A_L 75.097,142.85 r0 top
U3 "LM4041AIM3-1.2" MF03A_N 77.064,151.46 r180 top
U4 "RF430CL331HCPW" PW0014A_M 81.414,115.864 r90 top
U5 "TPS61220DCK" DCK0006A_N 94.996,108.712 r90 top
U6 "BMA280" LGA-12P 75.997,126.361 r90 top
U7 "TMP112AIDRL" DRL0006A 104.656,106.221 r0 top
U8 "ADS1292RIPBS" PBS0032A_N 88.697,141.853 r270 top
U9 "MSP430FR5889IRGCR" RGC0064B 90.221,124.562 r180 top
Y1 "FC-12M 32.7680KA-A3" Epson_FC-12M 90.729,117.45 r0 top
ZZ1 "This Assembly Note is for PCB labels only" AssemblyNoteLabel 35.992,195.631 r0 top
ZZ2 "These assemblies are ESD sensitive, ESD precautions shall be observed." AssemblyNote 35.992,192.865 r0 top
ZZ3 "These assemblies must be clean and free from flux and all contaminants. Use of no clean flux is not acceptable." AssemblyNote 35.992,190.616 r0 top
ZZ4 "These assemblies must comply with workmanship standards IPC-A-610 Class 2, unless otherwise specified." AssemblyNote 35.992,188.366 r0 top

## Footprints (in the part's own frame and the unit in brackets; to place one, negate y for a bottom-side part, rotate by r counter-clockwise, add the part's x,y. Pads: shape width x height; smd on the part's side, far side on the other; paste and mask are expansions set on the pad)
0402 [mm] "0402 from SM-752 data"
  rect 0.8x0.6 smd: 1(-0.6,0) 2(0.6,0)
  silkscreen extent -1.22,-0.52 1.22,0.52, body extent -0.55,-0.3 0.55,0.3, height 0.6
0603 [mm] "0603 from SM-752 data"
  rect 1x0.95 smd: 1(-0.8,0) 2(0.8,0)
  silkscreen extent -1.52,-0.69 1.52,0.69, body extent -0.87,-0.47 0.87,0.47, height 0.85
1206_190 [mm] "1206_190"
  rect 1.1x1.6 smd: 1(-1.7,0) 2(1.7,0)
  silkscreen extent -0.9,-1 0.9,1, body extent -1.75,-0.95 1.75,0.95, height 1.9
3216-18 [mm] "Medium density IPC, based on Kemet T495 dimensions"
  rect 1.8x1.25 smd: 1(-1.3,0) 2(1.3,0)
  silkscreen extent -2.49,-0.54 -2.49,0.54, body extent -1.7,-0.9 1.7,0.9, height 1.8
AssemblyNote [mm] "Assembly Note"
AssemblyNoteLabel [mm] "Assembly Note for PCB Labels"
Bumpon_SJ61A2 [mil] "3M Hemispherical Bumpon transparent"
  round 1 on Mech3: 0(0,0)
  silkscreen extent -192,-192 192,192, body extent -191,-192 193,192, height 250
DBV0005A_N [mm] "SOT23, 5-Leads, Body 2.9x1.6mm, Pitch 0.95mm, Lead Span 2.8mm, IPC Medium Density"
  rect 1.1x0.65 smd: 1(-1.2,0.95) 2(-1.2,0) 3(-1.2,-0.95) 4(1.2,-0.95) 5(1.2,0.95)
  silkscreen extent -0.25,-1.55 0.25,1.55, body extent -1.42,-1.46 1.42,1.46, height 1.08
DCK0006A_N [mm] "SOT23, 6-Leads, Body 2x1.3mm, Pitch 0.65mm, Lead Span 2.1mm, IPC Medium Density"
  rect 0.85x0.4 smd: 1(-0.95,0.65) 2(-0.95,0) 3(-0.95,-0.65) 4(0.95,-0.65) 5(0.95,0) 6(0.95,0.65)
  silkscreen extent -0.15,-1.1 0.15,1.1, body extent -1.14,-1 1.14,1, height 0.94
DRL0006A [mm] "SOTFL, 6-Flat Leads, Body 1.2x1.6x0.6mm, Pitch 0.5mm, TI recommended"
  rect 0.5x0.3 smd: 1(-0.75,0.5) 2(-0.75,0) 3(-0.75,-0.5) 4(0.75,-0.5) 5(0.75,0) 6(0.75,0.5)
  silkscreen extent -0.9,-0.95 0.9,0.95, body extent -0.85,-0.85 0.85,0.85, height 0.62
EPL3015 [mm] "COILCRAFT"
  rect 1.12x3.2 smd: 1(-1.04,0) 2(1.04,0)
  silkscreen extent -0.22,-1.65 0.23,1.68, body extent -1.6,-1.6 1.6,1.6, height 1.55
Epson_FC-12M [mm] "Epson"
  rect 0.7x1.4 smd: 1(-0.75,0) 2(0.75,0)
  body extent -1.05,-0.63 1.05,0.63, height 0.6
Fiducial10-20 [mm]
  round 1 smd mask+0.5: 1(0,0)
  Top Layer keep-out circle w1.178: c0,0 r0.5
Flat_Battery [mm]
  rrect50% 3.5x1.95 smd: 1(-2.667,0.127) 2(2.794,0.127)
  silkscreen extent -8.13,-25.53 22.73,-1.14, body extent -8.13,-25.53 22.73,-1.14, height 1
Keystone_1902C [mil] "Hex Standoff, 4-40 threaded, nylon"
  round 1 on Mech4: 0(0,0)
  body extent -145,-126 146,126, height 501
Keystone_2462 [mm] "2x AA Battery Holder, Through-hole mount"
  rect 1.8x1.8 hole 1.27: 1(-13.59,7.495)
  round 1.8 hole 1.27: 2(-13.59,-7.495)
  round 4.05 hole 3.55: 3(13.59,-7.495) 4(13.59,7.495)
  silkscreen extent -16.18,-16.46 43.33,16.46, body extent -16.31,-16.46 43.4,16.46, height 16
LGA-12P [mm]
  rect 0.3x0.35 smd mask+0.05: 1(-0.75,-0.775) 2(-0.25,-0.775) 3(0.25,-0.775) 4(0.75,-0.775) 7(0.75,0.775) 8(0.25,0.775) 9(-0.25,0.775) 10(-0.75,0.775)
  rect 0.35x0.3 smd mask+0.05: 5(0.775,-0.25) 6(0.775,0.25) 11(-0.775,0.25) 12(-0.775,-0.25)
  silkscreen extent -1.8,-1.8 -1.29,-1.3
MF03A_N [mm] "SOT23, 3-Leads, Body 2.9x1.3mm, Pitch 0.95mm, Lead Span 2.4mm, IPC Medium Density"
  rect 1.3x0.6 smd: 1(-1.05,0.95) 2(-1.05,-0.95) 3(1.05,0)
  silkscreen extent -1.18,-1.5 0.7,1.92, body extent -0.7,-1.5 0.7,1.5, height 1.12
MF05A_L [mm] "SOT23, 5-Leads, Body 2.9x1.6mm, Pitch 0.95mm, Lead Span 2.8mm, IPC High Density"
  rect 0.9x0.65 smd: 1(-1.2,0.95) 2(-1.2,0) 3(-1.2,-0.95) 4(1.2,-0.95) 5(1.2,0.95)
  silkscreen extent -1.32,-1.55 0.35,1.95, body extent -0.9,-1.55 0.9,1.55, height 1.19
NORCOMP_182-009-213R171 [mm] "Connector; D Subminiature 9 Position; Right Angle"
  rect 1.8x1.8 hole 1.092: 1(-5.54,-10.92)
  round 1.8 hole 1.092: 2(-2.77,-10.92) 3(0,-10.92) 4(2.77,-10.92) 5(5.54,-10.92) 6(-4.155,-8.08) 7(-1.385,-8.08) 8(1.385,-8.08) 9(4.155,-8.08)
  round 4.76 hole 3.05: 10(-12.495,-9.5) 11(12.495,-9.5)
  silkscreen extent -15.4,-12.4 15.4,6, body extent -15.41,-12.98 15.41,6.1, height 12.55
"NY PMS 440 0025 PH" [mm] "4-40 nylon screw and mounting hole"
  round 8 hole 3.2: 1(0,0)
  body extent -3.3,-3.3 3.3,3.3, height 2.69
PBS0032A_N [mil]
  rect 60x9 smd: 1(-124,68.9) 2(-124,49.21) 3(-124,29.53) 4(-124,9.84) 5(-124,-9.84) 6(-124,-29.53) 7(-124,-49.21) 8(-124,-68.9) 17(124,-68.9) 18(124,-49.21) 19(124,-29.53) 20(124,-9.84) 21(124,9.84) 22(124,29.53) 23(124,49.21) 24(124,68.9)
  rect 9x60 smd: 9(-68.9,-124) 10(-49.21,-124) 11(-29.53,-124) 12(-9.84,-124) 13(9.84,-124) 14(29.53,-124) 15(49.21,-124) 16(68.9,-124) 25(68.9,124) 26(49.21,124) 27(29.53,124) 28(9.84,124) 29(-9.84,124) 30(-29.53,124) 31(-49.21,124) 32(-68.9,124)
  silkscreen extent -104,-100 100,104, body extent -140,-140 140,140, height 48
PogoPad [mil] "No Solder Paste"
  round 70 smd paste-35: 1(0,0)
PW0014A_M [mm] "TSOP, 14-Leads, Body 5x4.4mm, Pitch 0.65mm, IPC Low Density"
  oval 2x0.35 smd: 1(-2.9,1.95) 2(-2.9,1.3) 3(-2.9,0.65) 4(-2.9,0) 5(-2.9,-0.65) 6(-2.9,-1.3) 7(-2.9,-1.95) 8(2.9,-1.95) 9(2.9,-1.3) 10(2.9,-0.65) 11(2.9,0) 12(2.9,0.65) 13(2.9,1.3) 14(2.9,1.95)
  silkscreen extent -1.5,-2.55 1.53,2.55, body extent -3.21,-2.5 3.21,2.5, height 0.98
RGC0064B [mm]
  oval 0.6x0.24 smd mask+0.07: 1(-4.4,3.75) 2(-4.4,3.25) 3(-4.4,2.75) 4(-4.4,2.25) 5(-4.4,1.75) 6(-4.4,1.25) 7(-4.4,0.75) 8(-4.4,0.25) 9(-4.4,-0.25) 10(-4.4,-0.75) 11(-4.4,-1.25) 12(-4.4,-1.75) 13(-4.4,-2.25) 14(-4.4,-2.75) 15(-4.4,-3.25) 16(-4.4,-3.75) 33(4.4,-3.75) 34(4.4,-3.25) 35(4.4,-2.75) 36(4.4,-2.25) 37(4.4,-1.75) 38(4.4,-1.25) 39(4.4,-0.75) 40(4.4,-0.25) 41(4.4,0.25) 42(4.4,0.75) 43(4.4,1.25) 44(4.4,1.75) 45(4.4,2.25) 46(4.4,2.75) 47(4.4,3.25) 48(4.4,3.75)
  oval 0.24x0.6 smd mask+0.07: 17(-3.751,-4.4) 18(-3.251,-4.4) 19(-2.751,-4.4) 20(-2.251,-4.4) 21(-1.75,-4.4) 22(-1.25,-4.4) 23(-0.75,-4.4) 24(-0.25,-4.4) 25(0.25,-4.4) 26(0.75,-4.4) 27(1.25,-4.4) 28(1.75,-4.4) 29(2.251,-4.4) 30(2.751,-4.4) 31(3.251,-4.4) 32(3.751,-4.4) 49(3.751,4.4) 50(3.251,4.4) 51(2.751,4.4) 52(2.251,4.4) 53(1.75,4.4) 54(1.25,4.4) 55(0.75,4.4) 56(0.25,4.4) 57(-0.25,4.4) 58(-0.75,4.4) 59(-1.25,4.4) 60(-1.75,4.4) 61(-2.251,4.4) 62(-2.751,4.4) 63(-3.251,4.4) 64(-3.751,4.4)
  rect 4.25x4.25 smd paste-2.112: 65(0,0)
  silkscreen extent -5.1,-5.1 5.1,5.1, body extent -4.57,-4.57 4.57,4.57, height 1.01
SOD-523F [mm] "COMCHIP"
  rect 0.6x0.8 smd paste-0.05: 1(-0.85,0) 2(0.85,0)
  silkscreen extent -1.92,-0.87 1.1,0.88, body extent -0.9,-0.5 0.9,0.5, height 0.85
TC2030-MCP-NL [mil] "TAG-CONNECT"
  round 31 smd paste-16: 1(-25,-50) 2(25,-50) 3(-25,0) 4(25,0) 5(-25,50) 6(25,50)
  round 25 hole 39 unplated: MH1(0,-100) MH2(-40,100) MH3(40,100)
  silkscreen extent -122,-195 118,195
TI_Symbol_Overlay_Small [mm]
  silkscreen extent -2.3,-2.23 2.3,2.24
TP_25MIL-SMT#1 [mm]
  round 0.635 smd mask-0.064: 1(0,0)
TP_25MIL-SMT#2 [mm]
  round 0.535 smd mask-0.064: 1(0,0)
TP_SM_1MM#1 [mm] "1mm Test Point, SMT"
  rrect50% 10x18 smd paste-0.5: 1(0,0)
TP_SM_1MM#2 [mm] "1mm Test Point, SMT"
  rrect50% 18x10 smd paste-0.5: 1(0,0)
TP_SM_1MM#3 [mm] "1mm Test Point, SMT"
  round 1 smd paste-0.5: 1(0,0)
Wurth_61201420621 [mm] "Header, 2.54mm, 7x2, SMT"
  rect 4x0.9 smd: 1(-3,7.62) 2(3,7.62) 3(-3,5.08) 4(3,5.08) 5(-3,2.54) 6(3,2.54) 7(-3,0) 8(3,0) 9(-3,-2.54) 10(3,-2.54) 11(-3,-5.08) 12(3,-5.08) 13(-3,-7.62) 14(3,-7.62)
  silkscreen extent -4.75,-12.7 4.4,12.7, body extent -4.75,-12.7 4.75,12.7, height 10.43

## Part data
1 2 3 4 5 6 7 8 9 10 11 12 13 14 15: "Test Point, O.025\""
BT1 BT2: library part Battery, "Battery, Lithium Polymer, 3V, 25mAh"
BT3 BT4: "2x AA Battery Holder, Through-hole mount"
C1 C2 C12: "CAP, TA, 10 µF, 10 V, +/- 10%, 3.4 ohm, SMD"
C3 C6 C7 C10 C11 C13 C14 C18 C19 C23 C24 C28 C36 C37 C40 C42 C48 C50 C52: "CAP, CERM, 0.1 µF, 10 V, +/- 10%, X5R, 0402"
C4 C27: "CAP, CERM, 1 µF, 6.3 V, +/- 20%, X5R, 0402"
C5 C20: "CAP, CERM, 2.2 µF, 16 V, +/- 10%, X5R, 0402"
C8 C26 C38: "CAP, CERM, 0.01 µF, 25 V, +/- 10%, X7R, 0402"
C9 C15: "CAP, TA, 1 µF, 16 V, +/- 10%, 9.3 ohm, SMD"
C16 C17 C21 C22 C34 C35: "CAP, CERM, 10 µF, 6.3 V, +/- 20%, X5R, 0402"
C25 C46 C49 C53 C54: "CAP, CERM, 2200 pF, 50 V, +/- 10%, X8R, 0402"
C29: "CAP, CERM, 0.47 µF, 6.3 V, +/- 10%, X5R, 0402"
C30: "CAP, CERM, 33 pF, 50 V, +/- 5%, C0G/NP0, 0603"
C31: "CAP, CERM, 39pF, 50V, +/-5%, C0G/NP0, 0402"
C32: "CAP, CERM, 100 µF, 10 V, +/- 20%, X5R, 1206_190"
C33: library part Capacitor, "CAP, CERM, xxxF, xxV, [TempCo], xx%, [PackageReference]"
C39 C41 C55 C56: "CAP, CERM, 1 µF, 16 V, +/- 10%, X5R, 0402"
C43: "CAP, CERM, 1500 pF, 50 V, +/- 10%, X7R, 0603"
C44 C57: "CAP, CERM, 3000 pF, 50 V, +/- 5%, C0G/NP0, 0603"
C45 C47: "CAP, CERM, 4700 pF, 10 V, +/- 10%, X5R, 0402"
C51: "CAP, CERM, 10 µF, 6.3 V, +/- 20%, X5R, 0603"
C58 C59: "CAP, CERM, 10 pF, 50 V, +/- 5%, C0G/NP0, 0603"
D1 D2: "Diode, Schottky, 35V, 0.1A, SOD-523F"
FID1 FID2 FID3: "Fiducial mark.  There is nothing to buy or mount."
H1 H2 H3 H4: "Bumpon, Hemisphere, 0.375 X 0.235, Black"
H5 H6 H7 H8: "Machine Screw, Round, #4-40 x 1/4, Nylon, Philips panhead"
H9 H10 H11 H12: "Standoff, Hex, 0.5\"L #4-40 Nylon"
J1: "Footprint for TC2030-MCP-NL"
J2: "Header(Shrouded), 2.54mm, 7x2, Gold, Black, SMT"
J3: "CONN DB9 FEMALE R/A SOLDER TH"
L1 L2 L3 L4 L5 L6: "Ferrite Bead, 600 ohm @ 100MHz, 0.2A, 0603"
L7: "Inductor, Shielded, Ferrite, 4.7uH, 1.2A, 0.14 ohm, SMD"
Logo1: library part TI_Logo, "Texas Instrument Corporate Signature"
R1 R2 R3 R4 R5 R7 R13 R14 R16 R19: "RES, 0, 5%, 0.063 W, 0402"
R6: "RES, 47 k, 5%, 0.063 W, 0402"
R8: "RES, 21.5 k, 1%, 0.063 W, 0402"
R9: "RES, 10.0 k, 1%, 0.063 W, 0402"
R10 R15 R20: "RES, 1.00 M, 1%, 0.1 W, 0402"
R11: "RES, 11.8 k, 1%, 0.063 W, 0402"
R12: "RES, 8.06 k, 1%, 0.063 W, 0402"
R17: "RES, 200 k, 1%, 0.1 W, 0402"
R18: "RES, 4.99 k, 1%, 0.063 W, 0402"
R21 R22: "RES, 100 k, 1%, 0.1 W, 0402"
R23 R30: "RES, 51.1 k, 1%, 0.063 W, 0402"
R24 R25 R28 R29: "RES, 10.0 M, 1%, 0.063 W, 0402"
R26 R27: "RES, 40.2 k, 1%, 0.063 W, 0402"
R31 R32: "RES, 3.3 k, 5%, 0.063 W, 0402"
TP1 TP2 TP3 TP4 TP5: library part TP_SM_1MM, "1mm Test Point, SMT"
TP6: library part PogoPad, "Pad for Pogo Pin Connector"
U1: "Single Output High PSRR LDO, 200 mA, Fixed 3 V Output, 2.7 to 5.5 V Input, 5-pin SOT-23 (DBV), -40 to 85 degC, Green (RoHS & no Sb/Br)"
U2: "Single Micropower Precision Op Amp"
U3: "Precision Micropower Shunt Voltage Reference, 3-pin SOT-23"
U4: library part RF430CL331H, "The Texas Instruments Dynamic NFC Interface Transponder RF430CL331H is an NFC Tag Type 4 device  that combines a wireless NFC interface and a wired SPI or I2C interface to connect the device to a host."
U5: "LOW INPUT VOLTAGE STEP-UP CONVERTER IN 6 PIN SC-70 PACKAGE, DCK0006A"
U6: library part BMA250, "14 bit, digital, triaxial acceleration sensor with intelligent on-chip motion triggered interrupt controller"
U7: "High-Accuracy, Low-Power, Digital Temperature Sensor With SMBus(TM)/Two-Wire Serial Interface, DRL0006A"
U8: "Low-Power, 2-Channel, 24-Bit Analog Front-End for Biopotential Measurement, PBS0032A"
U9: "Mixed-Signal Microcontrollers, RGC0064B"
Y1: "Crystal, 32.768kHz, 12.5pF, SMD"
ZZ1: library part AssemblyNoteLabel
ZZ2 ZZ3 ZZ4: library part AssemblyNote

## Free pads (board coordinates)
  round 0 hole 3.762 unplated: 0(87.909,88.062)

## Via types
v1: diameter 0.864, hole 0.406, Top Layer to Bottom Layer, 104 vias
v2: diameter 0.5, hole 0.2, Top Layer to Bottom Layer, 13 vias

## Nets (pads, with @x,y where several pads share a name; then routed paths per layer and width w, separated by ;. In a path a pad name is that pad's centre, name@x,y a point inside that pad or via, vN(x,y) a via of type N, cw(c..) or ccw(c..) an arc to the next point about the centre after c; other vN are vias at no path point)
3V: C3.1 C4.1 C35.1 R4.2 R5.2 R15.2 U1.1 U1.3 U5.4 | length 53.6
  Top Layer w0.254: U1.3@93.148,102.55 U1.3@93.226,102.628 ; 94.386,100.178 94.488,100.178 ; C3.1@94.669,102.55 C3.1@94.747,102.628 ; 96.663,106.02 96.663,106.061
  Top Layer w0.54: R15.2@93.015,104.496 96.663,104.496 ; U1.1@93.148,100.65 93.914,100.65 94.386,100.178 ; U1.3@93.148,102.55 C3.1@94.669,102.55 ; 94.488,100.178 97.841,100.178 98.349,100.686 98.349,101.702 95.901,104.15 96.663,104.496 ; C3.1@94.747,102.628 C4.1@96.017,102.628 96.017,104.034 ; U5.4@95.646,109.662 95.646,110.632 96.012,110.998 97.485,110.998 97.993,110.49 ; C35.1@95.85,105.41 96.663,105.41 ; 96.663,106.02 96.663,105.41 ; 96.663,106.061 97.282,106.68 97.282,107.696 97.587,108.001 97.587,110.084 97.993,110.49 ; v1(100.635,113.132) 97.993,110.49 ; v1(103.175,115.672) 105.969,115.672 112.76,122.463 R5.2@112.76,124.816 ; R4.2@112.741,126.365 112.76,126.346 R5.2@112.76,124.861 ; 96.663,104.496 96.663,105.41
  Bottom Layer w0.54: v1(100.635,113.132) v1(103.175,115.672)
ADS1292_DRDY: 9.1 U8.22 U9.16 | length 19.6
  Top Layer w0.254: U8.22@89.447,138.704 89.447,137.039 89.713,136.773 v1(89.713,136.754) ; U9.16@94.621,128.312 v1(96.003,128.312) 96.317,127.998 9.1@96.317,127.356
  Bottom Layer w0.254: v1(89.713,136.754) 89.713,134.602 93.657,130.658 ; 93.657,130.658 v1(96.003,128.312) 96.003,129.448 94.793,130.658 93.657,130.658
ADS1292_ELA: C52.1 J3.2 R30.1 TP4.1 | length 93.4
  Top Layer w1: R30.1@83.765,151.409 83.765,154.733 ; J3.2@87.527,160.454 87.528,157.302 ; C52.1@93.523,152.086 93.523,153.518 92.253,154.788 83.765,154.733 ; TP4.1@145.263,143.358 145.263,153.822 141.783,157.302 88.697,157.302 85.039,157.302 83.765,156.028 83.765,154.733
ADS1292_ERA: C48.1 J3.1 R23.1 TP3.1 | length 92.4
  Top Layer w0.54: R23.1@85.039,151.437 v1@85.039,153.67
  Top Layer w1: TP3.1@28.829,143.358 28.829,153.822 31.42,156.413 79.07,156.413 83.111,160.454 J3.1@84.757,160.454 ; v1(94.742,155.143) 94.793,155.092 C48.1@94.793,152.086
  Bottom Layer w0.54: v1@85.039,153.67 85.852,154.534
  Bottom Layer w1: J3.1@84.757,160.454 84.757,156.873 85.039,156.591 85.039,153.67 v1(85.039,153.314) ; 85.242,155.143 v1(94.742,155.143)
ADS1292_GPIO1: 6.1 U8.26 U9.14 | length 24.5
  Top Layer w0.254: U8.26@91.846,140.603 93.229,140.603 94.744,139.089 94.744,137.976 96.728,135.992 ; U9.14@94.621,127.312 95.345,127.312 97.067,125.59 v1@97.067,125.336 ; 6.1@95.301,131.674 96.171,131.674 v1(96.578,132.08) 96.734,132.236 96.734,135.992
  Bottom Layer w0.254: v1(96.578,132.08) 98.603,130.055 98.603,126.848 v1(97.079,125.324)
ADS1292_GPIO2: 7.1 U8.25 U9.25 | length 20.5
  Top Layer w0.254: U9.25@89.971,128.962 89.971,129.729 ; 89.97,129.73 89.97,131.626 91.186,132.842 95.758,132.842 96.317,133.401 96.317,135.839 94.29,137.866 94.29,138.8 92.987,140.103 U8.25@91.846,140.103 ; 89.97,131.166 7.1@91.491,131.166
ADS1292_IN1N: C46.1 R24.1 R25.2 U8.3 | length 12.8
  Top Layer w0.254: R24.1@89.297,152.202 89.967,152.202 ; U8.3@89.447,145.003 89.447,148.184 89.713,148.45 v1(89.713,148.946) ; 89.522,147.753 90.206,147.753 C46.1@90.891,148.438 ; v1(89.967,153.264) 89.967,152.202 ; R25.2@90.891,152.202 89.967,152.202
  Bottom Layer w0.254: v1(89.713,148.946) 89.713,150.932 89.967,151.186 v1(89.967,153.264)
ADS1292_IN1P: C54.1 R28.1 R29.2 U8.4 | length 9.1
  Top Layer w0.254: U8.4@88.947,145.003 88.947,149.246 89.408,149.708 C54.1@90.891,149.708 ; R28.1@89.297,150.932 90.094,150.932 ; 90.094,149.835 90.094,150.932 ; R29.2@90.891,150.932 90.094,150.932
ADS1292_IN2N: C44.1 R23.2 U8.5 | length 8.7
  Top Layer w0.254: C44.1@86.563,150.291 85.093,150.291 R23.2@85.039,150.237 85.039,149.447 85.395,149.092 86.279,149.092 86.563,148.807 88.447,146.924 U8.5@88.447,145.003
ADS1292_IN2P: C57.1 R30.2 U8.6 | length 9.5
  Top Layer w0.254: C57.1@82.241,150.263 83.711,150.263 R30.2@83.765,150.209 ; R30.2@83.711,150.209 83.711,149.359 84.433,148.638 86.091,148.638 87.947,146.782 U8.6@87.947,145.003
ADS1292_MAIN_CLKSEL: 14.1 U8.14 U9.32 | length 17.1
  Top Layer w0.254: U8.14@85.547,141.103 84.137,141.103 83.471,140.437 83.471,130.658 83.979,130.15 86.157,130.15 ; 14.1@86.157,130.912 86.157,130.15 ; U9.32@86.47,128.962 86.47,129.837 86.157,130.15
ADS1292_RESET: 8.1 U8.15 U9.31 | length 16.9
  Top Layer w0.254: 8.1@85.395,132.944 85.395,131.597 ; U8.15@85.547,140.603 85.527,140.583 84.433,140.583 83.925,140.075 83.925,132.128 84.455,131.597 85.395,131.597 ; U9.31@86.97,128.962 86.97,131.368 86.741,131.597 85.395,131.597
ADS1292_RESP_MODP/IN3N: R26.2 U8.32 | length 2.4
  Top Layer w0.254: U8.32@91.846,143.603 93.514,143.603 93.523,143.612 R26.2@93.523,144.328
ADS1292_RESP_MODP/IN3P: R27.2 TP6.1 U8.31 | length 13.4
  Top Layer w0.254: U8.31@91.846,143.103 93.568,143.103 R27.2@94.793,144.328 97.795,144.328 98.603,145.136 TP6.1@98.603,150.901
ADS1292_RLD: J3.4 R22.2 TP5.1 | length 3.2
  Top Layer w0.254: R22.2@103.267,147.168 104.953,147.168 v1(105.461,146.66)
  Bottom Layer w0.254: v1(105.461,146.66) 105.994,146.126
ADS1292_SPI_CS: 10.1 U8.18 U9.29 | length 14.1
  Top Layer w0.254: 85.487,135.23 10.1@86.665,135.23 ; 87.401,137.328 86.614,136.541 85.995,136.541 85.395,135.941 85.395,134.722 85.649,134.468 87.274,134.468 87.97,133.771 U9.29@87.97,128.962 ; 87.447,137.374 U8.18@87.447,138.704
ADS1292_SPI_DIN: 12.1 U8.19 U9.26 | length 17.3
  Top Layer w0.254: 12.1@82.093,135.23 82.093,135.992 82.347,136.246 v1(82.347,136.5) ; v1@87.947,136.766 U8.19@87.947,138.704 ; U9.26@89.471,128.962 89.471,132.143 v1(89.916,132.588)
  Bottom Layer w0.254: v1(82.347,136.5) v1(87.681,136.5) 87.681,134.823 v1(89.916,132.588)
ADS1292_SPI_DOUT: 11.1 U8.21 U9.27 | length 29.7
  Top Layer w0.254: U9.27@88.97,128.962 88.97,134.074 88.947,134.098 U8.21@88.947,138.704 88.947,140.052 v1(89.713,140.818) ; v1(100.127,147.93) 100.127,149.2 11.1@102.159,151.232
  Bottom Layer w0.254: v1(89.713,140.818) 93.777,144.882 97.079,144.882 v1(100.127,147.93)
ADS1292_SPI_SCLK: 13.1 U8.20 U9.28 | length 21.9
  Top Layer w0.254: 13.1@82.042,147.32 82.804,146.558 84.328,146.558 v1(84.836,146.05) ; v1(87.935,140.31) 88.443,139.802 88.443,133.96 88.47,133.932 U9.28@88.47,128.962
  Bottom Layer w0.254: v1(84.836,146.05) 84.836,143.408 v1(87.935,140.31)
ADS1292_START: 15.1 U8.16 U9.30 | length 15.2
  Top Layer w0.254: 84.379,137.77 15.1@85.141,137.77 ; U8.16@85.547,140.103 84.661,140.103 84.379,139.821 84.379,138.204 84.379,134.722 85.141,133.96 86.919,133.96 87.47,133.408 U9.30@87.47,128.962
ADS1292_VCAP1: C55.1 U8.11 | length 4.6
  Top Layer w0.254: C55.1@80.968,142.603 U8.11@85.547,142.603
ADS1292_VCAP2: C56.1 U8.27 | length 6.8
  Top Layer w0.254: U8.27@91.846,141.103 93.645,141.103 95.198,139.55 95.198,138.022 95.704,137.516 C56.1@96.225,137.516
ADS1292_VREFP: C50.1 C51.1 U8.9 | length 5.9
  Top Layer w0.254: C51.1@81.829,145.58 C51.1@81.534,145.58 81.642,145.472 C50.1@83.058,145.472 83.89,145.472 84.074,145.288 84.074,144.018 84.489,143.603 U8.9@85.547,143.603
ADS_AVCC: C22.1 C23.1 C24.1 C39.1 C40.1 L6.2 R8.2 R24.2 R28.2 U2.5 U8.12 | length 21.4
  Top Layer w0.254: U2.5@76.297,143.8 77.252,143.8 77.47,144.018 v1(77.47,144.78) ; v1(76.708,145.542) 76.757,145.493 77.929,145.493 78.537,146.101 R8.2@78.537,147.33 ; v1(78.486,136.906) 78.85,137.27 79.703,137.27 C23.1@79.761,137.212 ; v1(79.079,141.106) C39.1@81.031,141.106 ; L6.2@79.807,135.522 79.807,137.166 C23.1@79.761,137.212 ; v1(80.823,148.184) C24.1@80.823,150.378 ; C22.1@81.031,137.212 C23.1@79.761,137.212 ; C39.1@81.331,141.164 C40.1@82.601,141.164 83.54,142.103 U8.12@85.547,142.103 ; v1(88.097,149.362) R28.2@88.097,150.932 R24.2@88.097,152.202
ADS_AVSS: C22.2 C23.2 C24.2 C39.2 C40.2 C44.2 C50.2 C51.2 C55.2 C56.2 C57.2 J3.10 J3.11 R3.2 R9.1 R12.1 R25.1 R29.1 U2.2 U3.2 U8.10 U8.13 | length 43.8
  Top Layer w0.254: v1(68.206,123.489) R3.2@70.021,123.489 ; v1(72.811,142.85) U2.2@73.897,142.85 ; R12.1@75.951,148.117 74.981,149.088 74.981,151.74 75.677,152.436 78.929,152.436 80.757,152.436 ; v1@78.029,143.612 v1(78.283,143.612) 78.283,143.205 78.892,142.596 C55.2@79.761,142.596 ; v1(80.01,146.304) 80.01,144.272 80.302,143.98 C51.2@81.534,143.98 81.826,144.272 C50.2@83.058,144.272 83.058,143.51 83.464,143.104 84.074,143.104 U8.10@85.547,143.103 ; C24.2@80.823,151.578 v1(80.823,153.518) ; C22.2@81.031,138.412 79.761,138.412 79.761,139.906 81.031,139.906 82.197,139.906 C40.2@82.428,140.137 ; C57.2@82.241,151.863 v1(82.241,153.496) ; C40.2@82.601,139.964 82.601,140.068 83.894,141.362 ; 83.894,141.373 84.125,141.603 U8.13@85.547,141.603 ; C44.2@86.563,151.891 v1(86.563,153.416) ; R29.1@92.091,150.932 R25.1@92.091,152.202 v1(92.091,153.426) ; C56.2@97.425,137.516 97.425,136.916 v1(97.841,136.5)
  Top Layer w0.54: v1(104.191,135.484) R9.1@104.191,137.17
  other v1: 80.061,139.906
ADS_DVCC: C15.1 C19.1 C20.1 C21.1 C41.1 C42.1 L5.2 L6.1 U8.23 | length 24.7
  Top Layer w0.254: L6.1@79.807,133.972 80.061,133.972 v1(80.061,132.436) ; 89.713,135.484 89.713,134.376 89.967,134.122 C42.1@90.729,134.122 C41.1@91.999,134.122 C19.1@93.269,134.122 C20.1@94.539,134.122 ; 89.729,135.5 90.475,136.246 90.475,137.008 89.947,137.536 U8.23@89.947,138.704 ; C20.1@94.567,134.15 C20.1@94.539,134.122 ; v1(95.504,133.858) 95.504,133.896 95.278,134.122 C20.1@94.539,134.122 ; v1(97.841,132.944) C21.1@97.841,134.122 98.511,133.452 L5.2@99.835,133.452 99.835,134.176 100.889,135.23 100.889,139.294 100.127,140.056 C15.1@100.127,141.296
ANTENNA: D1.2 D2.2 R13.2 R14.2 | length 600.2
  Top Layer w0.4: v1(77.267,95.86) 78.029,96.622 98.857,96.622 98.857,73 76.505,73 76.505,97.13 99.365,97.13 99.365,72.492 75.997,72.492 75.997,97.638 99.873,97.638 99.873,71.984 75.438,71.984 75.438,98.044 76.251,98.857 76.251,103.631 76.806,104.055 77.897,104.055 ; v1(77.267,100.178) 77.267,101.702 77.876,102.311 84.633,102.311 84.963,102.641 D2.2@84.963,103.239 ; D1.2@77.897,106.379 77.897,104.055 ; R13.2@79.675,104.055 77.897,104.055 ; 81.199,102.311 R14.2@81.199,104.055
  Bottom Layer w0.4: 75.438,97.079 75.438,71.984 99.873,71.984 99.873,97.638 77.267,97.638 v1(77.267,100.178) ; 75.489,97.13 99.365,97.13 99.365,72.492 75.997,72.492 75.997,96.622 98.857,96.622 98.857,73 76.505,73 76.505,95.098 v1(77.267,95.86)
BMA_AVCC: C16.1 C37.1 L4.1 U6.7 | length 5.4
  Top Layer w0.254: C16.1@74.219,128.647 C37.1@75.489,128.647 ; U6.7@75.222,127.111 75.222,128.38 C37.1@75.489,128.647 ; L4.1@76.975,129.896 76.975,129.045 76.735,128.805 75.647,128.805 C37.1@75.489,128.647
BMA_DVCC: C17.1 C36.1 L3.2 L4.2 U6.1 U6.3 U6.11 | length 28.6
  Top Layer w0.254: U6.11@75.747,125.586 75.747,124.794 75.463,124.511 74.117,124.511 72.847,125.781 72.847,129.616 74.346,131.115 78.207,131.115 78.575,130.747 L4.2@78.575,129.896 78.575,129.096 79.553,128.118 L3.2@80.531,128.118 80.569,128.08 C17.1@80.569,126.224 C36.1@79.299,126.224 78.912,126.611 U6.3@76.772,126.611 ; U6.1@76.772,125.611 76.772,125.158 77.216,124.714 78.08,124.714 78.562,125.197 78.562,126.585
BMA_INT1: U6.5 U9.38 | length 11
  Top Layer w0.254: U6.5@76.247,127.136 76.247,127.657 76.382,127.792 v1(76.857,127.792) ; v1(82.347,126.848) 83.363,125.832 ; 83.383,125.812 U9.38@85.821,125.812
  Bottom Layer w0.254: v1(76.857,127.792) 77.826,127.792 78.844,126.774 79.39,126.774 79.464,126.848 v1(82.347,126.848)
